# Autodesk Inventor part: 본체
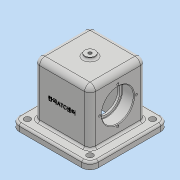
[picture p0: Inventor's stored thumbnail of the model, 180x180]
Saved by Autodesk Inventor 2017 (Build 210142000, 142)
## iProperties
Part Number: 본체
Material: 일반
Document SubType Name: Modeling
Designer: MRC
Density: 1 g/cm^3
Appearance: 기본값
Mass: 392.53 g
Surface Area: 721.846 cm^2
Volume: 392.53 cm^3
Author: MRC
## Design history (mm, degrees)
sketch "스케치1"
  geometry: L1 (-58, -58)-(58, -58); L2 (58, -58)-(58, 58); L3 (58, 58)-(-58, 58); L4 (-58, 58)-(-58, -58); L5 (-58, -58)-(58, 58); L6 (58, -58)-(-58, 58); 1 further point
  constraints: 12 end point, 2 midpoint, 2 parallel, 1 horizontal, 1 perpendicular
  dimensions: "d0" = 116 distance of L3.end L2.end; "d1" = 116 distance of L2.end L1.end
extrude "돌출1" new body sketch "스케치1" distance "d2" = 10; taper "d3" = 0 deg
fillet "모깎기1" dims "d4" = 12
fillet "모깎기2" dims "d5" = 12
fillet "모깎기3" dims "d6" = 3
sketch "스케치2"
  geometry: A1 r 12 centre (-46, 46) between (-46, 58) and (-58, 46) reference; A2 r 12 centre (46, 46) between (58, 46) and (46, 58) reference; A3 r 12 centre (-46, -46) between (-58, -46) and (-46, -58) reference; A4 r 12 centre (46, -46) between (46, -58) and (58, -46) reference; 5 further points
  constraints: 4 coincident
hole "구멍1" sketch "스케치2" at (-46, 46), (46, 46), (-46, -46), (46, -46) diameter "d7" = 9; stored, may be unused: countersink angle "d11" = 90 deg, drill point angle "d13" = 0 deg; dims "d8" = 6, "d9" = 4, "d10" = 2, "d12" = 8
sketch "스케치3"
  geometry: L1 (-41, 41)-(41, 41); L2 (41, 41)-(41, -41); L3 (41, -41)-(-41, -41); L4 (-41, -41)-(-41, 41); L5 (-41, 41)-(41, -41); L6 (41, 41)-(-41, -41); 1 further point
  constraints: 12 end point, 2 midpoint, 2 parallel, 1 horizontal, 1 perpendicular
  dimensions: "d14" = 82 distance of L2.end L3.end; "d15" = 82 distance of L1.end L2.end
extrude "돌출2" join sketch "스케치3" distance "d16" = 80; taper "d17" = 0 deg
fillet "모깎기4" dims "d18" = 8
fillet "모깎기5" dims "d19" = 8
fillet "모깎기6" dims "d20" = 3
sketch "스케치4"
  geometry: C1 r 7.5 at (0, 0); 1 further point
  constraints: 1 centre point, 1 coincident
  dimensions: "d21" = 15 diameter of C1
extrude "돌출3" join sketch "스케치4" distance "d22" = 4; taper "d23" = 0 deg
sketch "스케치6"
  geometry: L1 (21, -30)-(-21, -30); L2 (-21, -30)-(-21, 30); L3 (-21, 30)-(21, 30); L4 (21, 30)-(21, -30); L5 (-21, -30)-(21, 30); 2 further points
  constraints: 10 end point, 2 parallel, 1 horizontal, 1 midpoint, 1 perpendicular
  dimensions: "d24" = 42 distance of L2.end L3.end; "d25" = 60 distance of L1.end L2.end
extrude "돌출4" cut sketch "스케치6" distance "d26" = 80; taper "d27" = 0 deg
fillet "모깎기7" dims "d28" = 3
sketch "스케치7"
  geometry: 2 further points
  constraints: 1 coincident
hole "구멍2" sketch "스케치7" at (0, 0) diameter "d29" = 4.917; stored, may be unused: countersink angle "d33" = 90 deg, drill point angle "d35" = 0 deg; dims "d30" = 12, "d31" = 4, "d32" = 2, "d34" = 77.1
sketch "스케치12"
  geometry: L1 (-82, 33)-(12, 33); L2 (12, 25.5)-(12, 40.5) reference; L3 (-82, 79)-(-82, -13) reference; C1 r 20 at (-34, 33)
  constraints: 2 end point, 1 centre point, 1 midpoint, 1 point on line
  dimensions: "d47" = 40 diameter of C1; "d48" = 48 distance from line of L3 C1.centre
extrude "돌출8" cut sketch "스케치12" stored distance "d49" = 17; taper "d50" = 0 deg
sketch "스케치13"
  geometry: C1 r 20 at (-34, 33) reference; C2 r 23.5 at (-34, 33); 1 further point
  constraints: 1 centre point, 1 coincident
  dimensions: "d51" = 47 diameter of C2
extrude "돌출9" cut sketch "스케치13" distance "d52" = 17; taper "d53" = 0 deg
fillet "모깎기8" dims "d54" = 0.6
chamfer "모따기1" distance "d55" = 1; stored, may be unused: second distance "d56" = 2, angle "d57" = 45 deg
sketch "스케치14"
  geometry: L1 (-34, 33)-(-7, 33); L2 (-34, 33)-(-34, 6); L3 (-5, 60)-(-82, 60) reference; C1 r 24.5 at (-34, 33) reference; A1 r 27 centre (-34, 33) between (-7, 33) and (-34, 6); 5 further points
  constraints: 4 end point, 4 point on circle, 3 coincident, 1 centre point, 1 point on line, 1 vertical
  dimensions: "d58" = 54 diameter of A1
hole "구멍3" sketch "스케치14" at (-7, 33), (-34, 6), (-61, 33), (-34, 60) diameter "d59" = 3.242; stored, may be unused: countersink angle "d63" = 90 deg, drill point angle "d65" = 118 deg; dims "d60" = 8, "d61" = 4, "d62" = 2, "d64" = 10
sketch "스케치15"
  geometry: L1 (-13, -82)-(79, -82) reference; L2 (33, -82)-(33, 14); 2 further points
  constraints: 2 end point, 1 coincident, 1 midpoint, 1 vertical, 1 other
  dimensions: "d66" = 48 distance from line of point (33, -34) L1
feature "엠보싱1" sketch "스케치15" dims "d0" = 116, "d1" = 116, "d67" = 0.5, "d68" = 0
fillet "모깎기9" dims "d69" = 3
node "솔리드1"
mirror "미러1"
mirror "미러2"
